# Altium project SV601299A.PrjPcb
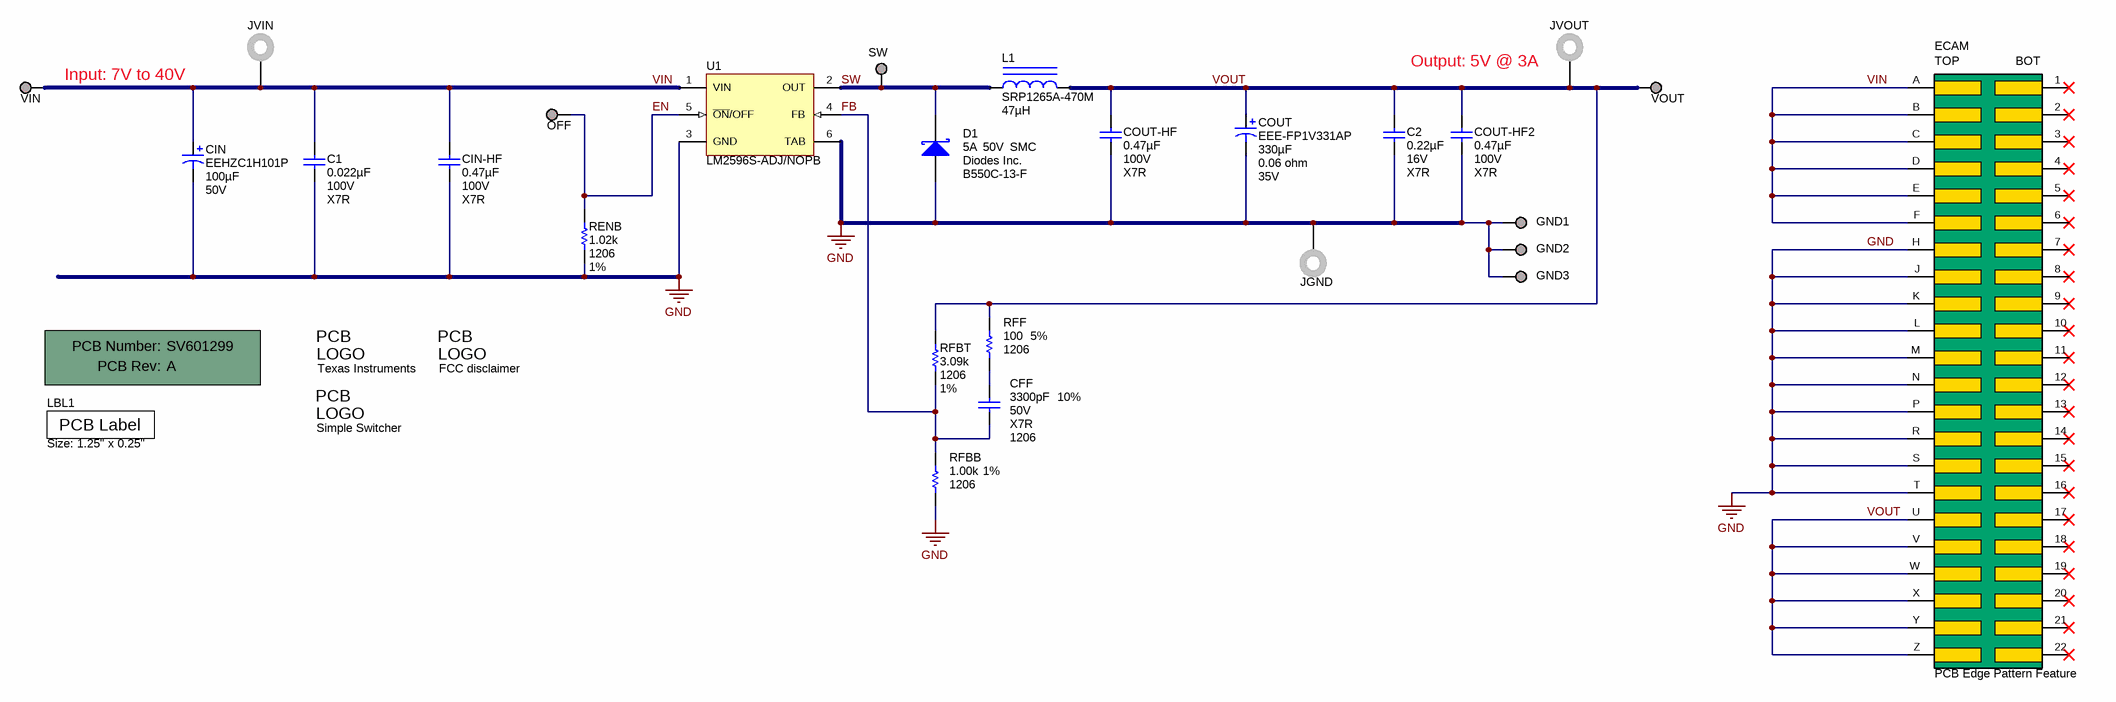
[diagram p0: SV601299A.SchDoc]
CopyrightYear: 2016; EVM_Orderable: LM2596S-ADJEVM; PCB_Layout: Arief Hernadi; PCB_Rev: A; PRJ_Customer: Public Release; PRJ_Engineer: Arief Hernadi; PRJ_Number: SV601299; PRJ_Title: LM2596S-ADJEVM; SCH_Rev: A; TechSupport: http://www.ti.com/support
1 sheet, 31 parts. Net scope: global (net labels, ports and power ports of the same name join across sheets).
Board file: SV601299A.PcbDoc

## Sheet SV601299A.SchDoc
size 431 x 279 mm; Date: Not shown in title block; ApprovedBy: Not shown in title block; CheckedBy: Not shown in title block; Author: Not shown in title block; CompanyName: Not shown in title block; Engineer: Not shown in title block; Organization: Not shown in title block; Address1: Not shown in title block; Address2: Not shown in title block; Address3: Not shown in title block; Address4: Not shown in title block; DocumentNumber: 1; Revision: Use project parameter SCH_Rev; SheetNumber: 1; SheetTotal: 1; PageSetup: Record=PageOptions¦CenterHorizontal=True¦CenterVertical=True¦PrintScale=0.62¦XCorrection=1.00¦YCorrection=1.00¦PrintKind=0¦BorderSize=5000000¦LeftOffset=0¦BottomOffset=0¦Orientation=2¦PaperLength=1000¦PaperWidth=1000¦Scale=100¦PaperSource=15¦PrintQuality=600¦MediaType=1¦DitherType=10¦PrintScaleMode=1¦PaperKind=Letter

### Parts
!PCB  Printed Circuit Board  (value not drawn)  (mechanical)
C1  ValueDisplayed: 0.022µF  Value2: 100V  TempCo: X7R  [0603]  (hidden comment: C1608X7R2A223K080AA)
C2  ValueDisplayed: 0.22µF  Value2: 16V  TempCo: X7R  [0603]  (hidden comment: C1608X7R1C224K080AC)
CFF  ValueDisplayed: 3300pF  Tolerance_%: 10%  Value2: 50V  TempCo: X7R  [1206]  (hidden comment: 12065C332KAT2A)
CIN  ValueDisplayed: 100µF  Value2: 50V  [SM_RADIAL_10BMM]  (hidden comment: EEHZC1H101P)
CIN-HF  ValueDisplayed: 0.47µF  Value2: 100V  TempCo: X7R  [1206_180]  (hidden comment: C3216X7R2A474K160AA)
COUT  ValueDisplayed: 330µF  Value1: 0.06 ohm  Value2: 35V  [CAPAE1030X1080]  (hidden comment: EEE-FP1V331AP)
COUT-HF  ValueDisplayed: 0.47µF  Value2: 100V  TempCo: X7R  [1206_180]  (hidden comment: C3216X7R2A474K160AA)
COUT-HF2  ValueDisplayed: 0.47µF  Value2: 100V  TempCo: X7R  [1206_180]  (hidden comment: C3216X7R2A474K160AA)
D1  B550C-13-F  value 50V  Manufacturer: Diodes Inc.  Value1: 5A  [SMC]
ECAM  PCB Edge Pattern Feature  [EDAC 2X22_am]  (no BOM)
GND1  Suggest using a net name here  [Keystone1502-2]  (value not drawn)
GND2  Suggest using a net name here  [Keystone1502-2]  (value not drawn)
GND3  Suggest using a net name here  [Keystone1502-2]  (value not drawn)
JGND  575-8  [Keystone575-8]  (value not drawn)
JVIN  575-8  [Keystone575-8]  (value not drawn)
JVOUT  575-8  [Keystone575-8]  (value not drawn)
L1  ValueDisplayed: 47µH  [SRP1265A]  (hidden comment: SRP1265A-470M)
LBL1  Size: 1.25" x 0.25"  [Label_1250x250]
Logo1  Texas Instruments  [TI_Stacked_Overlay_Medium]  (no BOM)
Logo3  FCC disclaimer  [FCC_disclaimer]  (no BOM)
Logo4  Simple Switcher  [SS_Overlay_Medium]  (no BOM)
OFF  Suggest using a net name here  [Keystone1502-2]  (value not drawn)
RENB  ValueDisplayed: 1.02k  Value1: 1%  [1206]  (hidden comment: CRCW12061K02FKEA)
RFBB  ValueDisplayed: 1.00k  Value1: 1%  [1206]  (hidden comment: ERJ-8ENF1001V)
RFBT  ValueDisplayed: 3.09k  Value1: 1%  [1206]  (hidden comment: CRCW12063K09FKEA)
RFF  ValueDisplayed: 100  Value1: 5%  [1206]  (hidden comment: CRCW1206100RJNEA)
SW  Suggest using a net name here  [Keystone1502-2]  (value not drawn)
U1  LM2596S-ADJ/NOPB  [TS5B_N]
VIN  Suggest using a net name here  [Keystone1502-2]  (value not drawn)
VOUT  Suggest using a net name here  [Keystone1502-2]  (value not drawn)

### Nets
GND: C1.2 C2.2 CIN.2(-) CIN-HF.2 COUT.2(-) COUT-HF.2 COUT-HF2.2 D1.2(A) ECAM.H ECAM.J ECAM.K ECAM.L ECAM.M ECAM.N ECAM.P ECAM.R ECAM.S ECAM.T GND1.1 GND2.1 GND3.1 JGND.1 RENB.1 RFBB.1 U1.3(GND) U1.6(TAB)
EN: OFF.1 RENB.2 U1.5(~{ON}/OFF)
FB: CFF.1 RFBB.2 RFBT.1 U1.4(FB)
SW: D1.1(K) L1.1 SW.1 U1.2(OUT)
VIN: C1.1 CIN.1(+) CIN-HF.1 ECAM.A ECAM.B ECAM.C ECAM.D ECAM.E ECAM.F JVIN.1 U1.1(VIN) VIN.1
VOUT: C2.1 COUT.1(+) COUT-HF.1 COUT-HF2.1 ECAM.U ECAM.V ECAM.W ECAM.X ECAM.Y ECAM.Z JVOUT.1 L1.2 RFBT.2 RFF.1 VOUT.1
NetCFF_2: CFF.2 RFF.2

Not connected (* = marked no-connect by the designer): ECAM 1* 2* 3* 4* 5* 6* 7* 8* 9* 10* 11* 12* 13* 14* 15* 16* 17* 18* 19* 20* 21* 22*

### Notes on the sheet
- (near VIN) Input: 7V to 40V
- (near JVOUT) Output: 5V @ 3A

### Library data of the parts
!PCB = PCB: Manufacturer: Any; PartNumber: SV601299; SymbolCreator: a0412235
C1 = C1608X7R2A223K080AA: CAP, CERM, 0.022 µF, 100 V, +/- 10%, X7R, 0603; Manufacturer: TDK; Polarized: N; CompType: Capacitor; Value: 0.022uF; U/M: EA; Cap_F: 0.000000022; Tolerance_%: 10; ESR_ohm: 0.037; Value1: 0.037 ohm; VDC_V: 100; TaMin_C: -55; TaMax_C: 125; AEC Category: Q200; SizeArea_mm2: 1.28; SizeAreaWB_mm2: 4.68; SizeX_mm: 1.6; SizeY_mm: 0.8; SizeZ_mm: 1
C2 = C1608X7R1C224K080AC: CAP, CERM, 0.22 µF, 16 V, +/- 10%, X7R, 0603; Manufacturer: TDK; Polarized: N; CompType: Capacitor; Value: 0.22uF; U/M: EA; Cap_F: 0.00000022; Tolerance_%: 10; ESR_ohm: 0.0125; Value1: 0.0125 ohm; VDC_V: 16; TaMin_C: -55; TaMax_C: 125; AEC Category: Q200; SizeArea_mm2: 1.28; SizeAreaWB_mm2: 4.68; SizeX_mm: 1.6; SizeY_mm: 0.8; SizeZ_mm: 1
CFF = 12065C332KAT2A: CAP, CERM, 3300 pF, 50 V, +/- 10%, X7R, 1206; Manufacturer: AVX; Polarized: N; CompType: Capacitor; Value: 3300pF; U/M: EA; Cap_F: 0.0000000033; ESR_ohm: 0.216; Value1: 0.216 ohm; VDC_V: 50; TaMin_C: -55; TaMax_C: 125; AEC Category: Q200
CIN = EEHZC1H101P: CAP, Polymer Hybrid, 100 µF, 50 V, +/- 20%, 28 ohm, 10x10 SMD; Manufacturer: Panasonic; Polarized: Y; CompType: Capacitor; Value: 100uF; U/M: EA; Cap_F: 0.0001; Tolerance_%: 20; Value1: 28 ohm; VDC_V: 50; ESR_ohm: 28; IRMS_A: 1.6; TaMin_C: -55; TaMax_C: 125; AEC Category: Q200
CIN-HF COUT-HF COUT-HF2 = C3216X7R2A474K160AA: CAP, CERM, 0.47 µF, 100 V, +/- 10%, X7R, 1206; Manufacturer: TDK; Polarized: N; CompType: Capacitor; Value: 0.47uF; U/M: EA; Cap_F: 0.00000047; Tolerance_%: 10; ESR_ohm: 0.007558; Value1: 0.007558 ohm; VDC_V: 100; IRMS_A: 2.64716; TaMin_C: -55; TaMax_C: 125; AEC Category: Q200; SizeArea_mm2: 5.12; SizeAreaWB_mm2: 10.92; SizeX_mm: 3.2; SizeY_mm: 1.6; SizeZ_mm: 1.8
COUT = EEE-FP1V331AP: CAP, AL, 330 µF, 35 V, +/- 20%, 0.06 ohm, SMD; Manufacturer: Panasonic; Polarized: Y; CompType: Capacitor; Value: 330uF; U/M: EA; Cap_F: 0.00033; Tolerance_%: 20; VDC_V: 35; ESR_ohm: 0.06; IRMS_A: 1.19; TaMin_C: -55; TaMax_C: 105; Cap_Case: 10x10.3mm; AEC Category: Q200
D1 = B550C-13-F: Diode, Schottky, 50 V, 5 A, SMC; U/M: EA; Vf_V: 0.7; Value2: 0.7V; Io_A: 5; Vr_V: 50; TJmax_C: 125; RJC_CperW: 10; AEC Category: Q101
ECAM = EDAC 2x22_AM: EDAC Edge 2x22 Contact Edge Connector Feature; SymbolCreator: A0413350; CompType: PCB Feature; U/M: none
GND1-GND3 OFF SW VIN VOUT = 1502-2: Terminal, Turret, TH, Double; Manufacturer: Keystone; CompType: Turret Terminal; U/M: EA
JGND JVIN JVOUT = 575-8: Standard Banana Jack, Uninsulated, 8.9mm; Manufacturer: Keystone; CompType: Connector; U/M: EA
L1 = SRP1265A-470M: Inductor, Shielded, 47 µH, 6.5 A, 0.076 ohm, AEC-Q200 Grade 0, SMD; Manufacturer: Bourns; Value: 47uH; Ind_H: 47.0E-6; Imax_A: 6.5; Irms: 6.5A @ 40C rise; Isat: 9.5A @ 20% inductance drop; DCR_ohm: 0.076; Value2: 6.5A; AEC Category: Q200; AEC Qualified: Y; AEC Grade: 0
LBL1 = THT-13-457-10: Thermal Transfer Printable Labels, 1.250" W x 0.250" H - 10,000 per roll; Manufacturer: Brady; SymbolCreator: a0412235; CompType: Label
Logo1 = TI_Logo: Texas Instrument Corporate Signature; SymbolCreator: codlsc
Logo3 = FCC_disclaimer: SymbolCreator: codlsc
Logo4 = SimpleSwitcher: Simple Switcher Logo; SymbolCreator: a0412235
RENB = CRCW12061K02FKEA: RES, 1.02 k, 1%, 0.25 W, 1206; Manufacturer: Vishay-Dale; CompType: Resistor; Value: 1.02k; Res_ohm: 1020; Value_Code: 1k02; Tolerance_%: 1; Power_W: 0.25; Value2: 0.25W; VDC_V: 200; TempCo: 100 ppm/C; EIA_Code: E96; U/M: EA; AEC Category: Q200
RFBB = ERJ-8ENF1001V: RES, 1.00 k, 1%, 0.25 W, 1206; Manufacturer: Panasonic; CompType: Resistor; Value: 1.00k; Res_ohm: 1000; Value_Code: 1k00; Tolerance_%: 1; Power_W: 0.25; Value2: 0.25W; VDC_V: 200; TempCo: 100 ppm/C; EIA_Code: E96; U/M: EA; AEC Category: Q200
RFBT = CRCW12063K09FKEA: RES, 3.09 k, 1%, 0.25 W, 1206; Manufacturer: Vishay-Dale; CompType: Resistor; Value: 3.09k; Res_ohm: 3090; Value_Code: 3k09; Tolerance_%: 1; Power_W: 0.25; Value2: 0.25W; VDC_V: 200; TempCo: 100 ppm/C; SizeArea_mm2: 5.12; SizeX_mm: 3.2; SizeY_mm: 1.6; SizeZ_mm: 1.35; EIA_Code: E96; U/M: EA; AEC Category: Q200
RFF = CRCW1206100RJNEA: RES, 100, 5%, 0.25 W, 1206; Manufacturer: Vishay-Dale; CompType: Resistor; Value: 100; Value_Code: 100R; Tolerance_%: 5; Power_W: 0.25; Value2: 0.25W; VDC_V: 200; TempCo: 200 ppm/C; EIA_Code: E24; U/M: EA; AEC Category: Q200
U1 = LM2596S-ADJ/NOPB: SIMPLE SWITCHER® Power Converter 150 KHz 3A Step-Down Voltage Regulator, 5-pin TO-263, Pb-Free; Manufacturer: Texas Instruments; PackageTopMarking: NSUZXYTTE#*LM2596S*-ADJ P+; PowerWise: N

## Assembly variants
001: not fitted CFF LBL1 RFF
